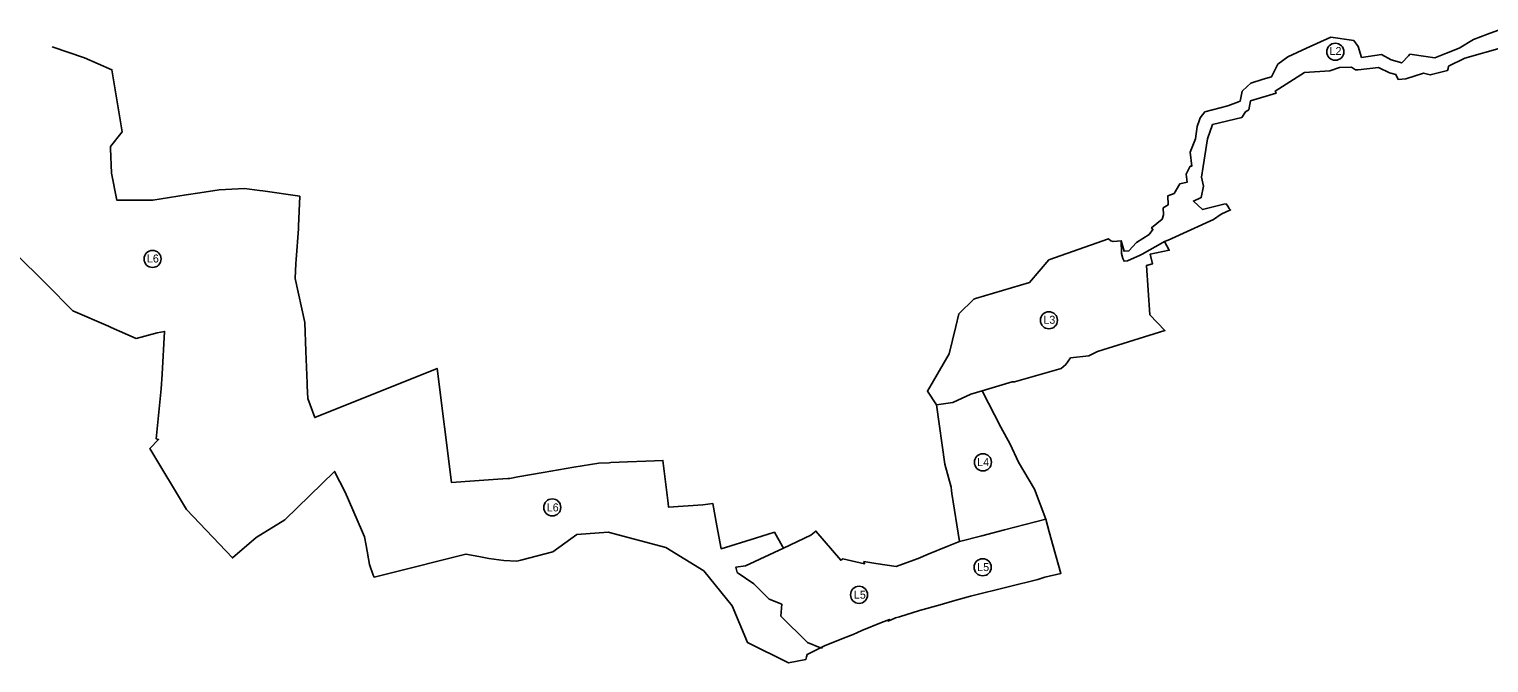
# Model space of a CAD drawing. Extents: x -445081 to -429827, y -1135509 to -1130103.
# Drawn here: x -443832 to -441644, y -1133015 to -1132066 of the extents above; entities that cross this region are included whole.
import ezdxf

# ---------------------------------------------------------------- set-up
doc = ezdxf.new("R2010")
doc.units = 0
for name, color, linetype in [('Vrstva 32', 7, 'Continuous'), ('Vrstva 33', 7, 'Continuous'), ('Vrstva 36', 7, 'Continuous')]:
    doc.layers.add(name, color=color, linetype=linetype)

msp = doc.modelspace()

# ---------------------------------------------------------------- linework, layer by layer
at = {"layer": 'Vrstva 32'}
msp.add_lwpolyline([(-442471.6, -1132628.2), (-442447, -1132625.1), (-442420.2, -1132612.5), (-442403.1, -1132607.3), (-442358.4, -1132593.7), (-442358.4, -1132593.7), (-442354.7, -1132593.7), (-442284.9, -1132574), (-442277.9, -1132567.9), (-442270.6, -1132557.9), (-442243.2, -1132554.9), (-442230.4, -1132548.5), (-442129.2, -1132516.8), (-442151.6, -1132493.3), (-442156.8, -1132419.4), (-442147.8, -1132417.1), (-442151.1, -1132402.4), (-442122.6, -1132396.7), (-442129.7, -1132383.8), (-442132.1, -1132384.9), (-442163.5, -1132402.4), (-442166.4, -1132404.1), (-442185.4, -1132412.8), (-442190.5, -1132413.2), (-442190.5, -1132413.2), (-442192.4, -1132409.2), (-442194.2, -1132401.6), (-442194.6, -1132382.5), (-442206.7, -1132383.5), (-442210.1, -1132382.7), (-442213.7, -1132379.6), (-442303.1, -1132411), (-442332, -1132445), (-442413.2, -1132469.2), (-442415.9, -1132470.2), (-442438.4, -1132492.1), (-442442.6, -1132510.8), (-442452.5, -1132552.2), (-442485.4, -1132607.7)], close=True, dxfattribs=at)
for points in [[(-442485.4, -1132607.7), (-442471.6, -1132628.2), (-442447, -1132625.1), (-442420.2, -1132612.5), (-442403.1, -1132607.3), (-442358.4, -1132593.7), (-442354.7, -1132593.7), (-442284.9, -1132574), (-442277.9, -1132567.9), (-442270.6, -1132557.9), (-442243.2, -1132554.9), (-442230.4, -1132548.5), (-442129.2, -1132516.8), (-442151.6, -1132493.3), (-442156.8, -1132419.4), (-442147.8, -1132417.1), (-442151.1, -1132402.4), (-442122.6, -1132396.7), (-442129.7, -1132383.8), (-442132.1, -1132384.9), (-442163.5, -1132402.4), (-442166.4, -1132404.1), (-442185.4, -1132412.8), (-442190.5, -1132413.2), (-442192.4, -1132409.2), (-442194.2, -1132401.6), (-442194.6, -1132382.5), (-442206.7, -1132383.5), (-442210.1, -1132382.7), (-442213.7, -1132379.6), (-442303.1, -1132411), (-442332, -1132445), (-442413.2, -1132469.2), (-442415.9, -1132470.2), (-442438.4, -1132492.1), (-442442.6, -1132510.8), (-442452.5, -1132552.2), (-442485.4, -1132607.7)], [(-442309, -1132886.8), (-442285.2, -1132881.1), (-442296.6, -1132840.1), (-442302.5, -1132818.9), (-442307.9, -1132799.8), (-442369.7, -1132815.7), (-442403.5, -1132824.5), (-442437.2, -1132833.3), (-442454.6, -1132840.1), (-442484, -1132852.3), (-442499.3, -1132858.8), (-442522.6, -1132867.2), (-442532.1, -1132870.8), (-442562.6, -1132866.1), (-442580.6, -1132863.3), (-442579.6, -1132866.6), (-442612, -1132859.2), (-442615.2, -1132861.2), (-442652.5, -1132817.5), (-442660.2, -1132823.9), (-442701.1, -1132843), (-442758.2, -1132869.6), (-442772.4, -1132871.4), (-442770.3, -1132879.6), (-442745.5, -1132896.6), (-442722.7, -1132919.5), (-442703.6, -1132927.2), (-442704.9, -1132945.1), (-442665, -1132984.7), (-442645.8, -1132992.7), (-442643.5, -1132991.5), (-442639.5, -1132989.6), (-442611.1, -1132978), (-442596.7, -1132972.3), (-442583.4, -1132966.7), (-442554.2, -1132954.6), (-442542.3, -1132949.9), (-442544.6, -1132952.4), (-442540.7, -1132951), (-442532.9, -1132947.8), (-442527, -1132946), (-442497.2, -1132936.8), (-442466.4, -1132928.3), (-442447.5, -1132922.7), (-442420.8, -1132914.9), (-442364.2, -1132900.9), (-442319.8, -1132890.2), (-442309, -1132886.8)], [(-442285.2, -1132881.1), (-442296.6, -1132840.1), (-442302.5, -1132818.9), (-442307.9, -1132799.8), (-442307.9, -1132799.8), (-442369.7, -1132815.7), (-442403.5, -1132824.5), (-442403.5, -1132824.5), (-442437.2, -1132833.3), (-442454.6, -1132840.1), (-442484, -1132852.3), (-442499.3, -1132858.8), (-442522.6, -1132867.2), (-442532.1, -1132870.8), (-442562.6, -1132866.1), (-442580.6, -1132863.3), (-442579.6, -1132866.6), (-442612, -1132859.2), (-442615.2, -1132861.2), (-442652.5, -1132817.5), (-442660.2, -1132823.9), (-442660.2, -1132823.9), (-442701.1, -1132843), (-442758.2, -1132869.6), (-442758.2, -1132869.6), (-442772.4, -1132871.4), (-442770.3, -1132879.6), (-442745.5, -1132896.6), (-442722.7, -1132919.5), (-442703.6, -1132927.2), (-442704.9, -1132945.1), (-442665, -1132984.7), (-442645.8, -1132992.7), (-442642.5, -1132992.5)]]:
    msp.add_lwpolyline(points, dxfattribs=at)
at = {"layer": 'Vrstva 33'}
for points in [[(-442194.6, -1132382.5), (-442190.4, -1132398.3), (-442183.1, -1132397.7), (-442172, -1132385.1), (-442152.9, -1132373.3), (-442147.1, -1132365.7), (-442149.2, -1132363), (-442133.5, -1132350.3), (-442131.5, -1132343.5), (-442131.9, -1132333.2), (-442124.4, -1132328.7), (-442124.8, -1132315.1), (-442115.4, -1132311.6), (-442106.8, -1132297.2), (-442095.8, -1132294.5), (-442097.1, -1132282.6), (-442091.2, -1132270.8), (-442088.8, -1132270.5), (-442091.5, -1132249.7), (-442083.1, -1132229.6), (-442080.6, -1132211.1), (-442077.8, -1132202.9), (-442076.1, -1132198.1), (-442069.2, -1132189.5), (-442035, -1132180.3), (-442018.8, -1132174.2), (-442016.2, -1132173.2), (-442013.2, -1132158.4), (-442005.7, -1132151.3), (-442000.4, -1132146.2), (-441982, -1132140.6), (-441969.2, -1132136.8), (-441960.1, -1132118.1), (-441944.8, -1132106.9), (-441916.7, -1132094), (-441880.5, -1132077.3), (-441846.1, -1132082.3), (-441839.3, -1132091.3), (-441834.4, -1132107.8), (-441804.5, -1132103.5), (-441790.2, -1132111.6), (-441774.1, -1132116), (-441764, -1132105.2), (-441761.9, -1132102.9), (-441737.8, -1132106.4), (-441724.3, -1132108.4), (-441707.1, -1132101.5), (-441688.2, -1132093.9), (-441666.7, -1132080.9), (-441666.7, -1132080.9), (-441645.6, -1132073.1), (-441624.9, -1132065.5)], [(-443797.6, -1132091.8), (-443748.9, -1132108.2), (-443748.9, -1132108.2), (-443707.9, -1132126.3), (-443692.6, -1132219.1), (-443692.6, -1132219.1), (-443710.2, -1132241.2), (-443710.1, -1132244.3), (-443708.7, -1132281), (-443700.4, -1132321.8), (-443646.8, -1132321.8), (-443596.6, -1132313.9), (-443576.1, -1132310.6), (-443547.1, -1132306), (-443509, -1132304), (-443486.5, -1132307.1), (-443481.6, -1132307.8), (-443426.4, -1132315.9), (-443428.4, -1132360.5), (-443428.3, -1132364.5), (-443431.7, -1132410.4), (-443432.1, -1132416.4), (-443433.4, -1132439.1), (-443418.8, -1132505.1), (-443417.1, -1132548.1), (-443415.2, -1132596), (-443415, -1132599.7), (-443414.3, -1132618.9), (-443403.8, -1132647.4), (-443220.4, -1132573.8), (-443199, -1132744.6), (-443199, -1132744.6), (-443164.2, -1132742.2), (-443129.3, -1132739.8), (-443114.3, -1132738.9), (-443111.3, -1132738.6), (-443099.5, -1132736.5), (-443061.5, -1132729.8), (-443061.5, -1132729.8), (-443061.5, -1132729.8), (-443015.2, -1132721.8), (-442977.8, -1132715.9), (-442962.3, -1132715.2), (-442959.8, -1132714.9), (-442935.1, -1132714), (-442907.7, -1132712.9), (-442894.7, -1132712.4), (-442881.8, -1132711.8), (-442874.1, -1132775.7), (-442873.5, -1132781.6), (-442822.1, -1132778.2), (-442806.9, -1132776.4), (-442800.9, -1132809.5), (-442794.6, -1132844), (-442743.2, -1132828), (-442714.7, -1132819.2), (-442714.7, -1132819.2), (-442702.4, -1132840.6), (-442701.1, -1132843)], [(-441623, -1132093), (-441679.7, -1132109.1), (-441679.7, -1132109.1), (-441703.9, -1132121.1), (-441704.7, -1132124.2), (-441705.4, -1132127.2), (-441731.3, -1132133.9), (-441741.6, -1132131.3), (-441768.2, -1132139.7), (-441779.6, -1132140.8), (-441782.8, -1132133.6), (-441792.7, -1132130.8), (-441809.2, -1132122.8), (-441839.7, -1132126.2), (-441843.4, -1132126.6), (-441849.5, -1132122.5), (-441867.2, -1132122.8), (-441881.8, -1132128), (-441919.7, -1132130.2), (-441925.5, -1132133.9), (-441963.7, -1132158.2), (-441962.5, -1132161.6), (-442000.9, -1132172.9), (-442003.5, -1132186.2), (-442008.5, -1132189.4), (-442013.7, -1132197.7), (-442057.7, -1132208.4), (-442065.5, -1132229.9), (-442071.7, -1132271.2), (-442074.1, -1132287), (-442071.5, -1132300.9), (-442074.6, -1132317.9), (-442086.4, -1132323), (-442072.7, -1132335.8), (-442041.1, -1132327.7), (-442037.4, -1132327.3), (-442034.9, -1132330.7), (-442032.7, -1132334), (-442030.8, -1132336.4), (-442045, -1132342.9), (-442056.5, -1132350.9), (-442124.4, -1132381.4), (-442129.7, -1132383.8)], [(-442645.8, -1132992.7), (-442648.5, -1132994), (-442665.8, -1133002.6), (-442666.7, -1133006), (-442667.8, -1133010.1), (-442693.6, -1133014.9), (-442755.1, -1132984.5), (-442778, -1132929.5), (-442820.7, -1132876.9), (-442877.4, -1132842.4), (-442963.8, -1132819.4), (-443011, -1132822.8), (-443046.8, -1132848.6), (-443095, -1132861.1), (-443101, -1132862.6), (-443120.6, -1132861.5), (-443143, -1132858.5), (-443157.7, -1132855.7), (-443177.3, -1132852.1), (-443207.3, -1132859.6), (-443264.6, -1132874), (-443314.9, -1132886.6), (-443316.1, -1132883.4), (-443321.9, -1132867.7), (-443327, -1132839), (-443329.2, -1132826.1), (-443332.2, -1132819.2), (-443333.7, -1132815.9), (-443333.7, -1132815.9), (-443333.7, -1132815.9), (-443333.7, -1132815.9), (-443358.3, -1132759.2), (-443374.2, -1132728.1), (-443374.2, -1132728.1), (-443448.7, -1132800.5), (-443491.7, -1132827.4), (-443527.2, -1132857.8), (-443596, -1132785.4), (-443651, -1132694), (-443638, -1132680.3), (-443638, -1132680.3), (-443641.5, -1132679.3), (-443633.9, -1132604.4), (-443633.9, -1132604.4), (-443632.6, -1132582.2), (-443632.6, -1132582.2), (-443629, -1132518.3), (-443629, -1132518.3), (-443639.9, -1132520.7), (-443671.8, -1132528.9), (-443709.2, -1132512.6), (-443713.3, -1132510.7), (-443713.3, -1132510.7), (-443713.3, -1132510.7), (-443766.7, -1132487.4), (-443806.2, -1132447.4), (-443853.9, -1132399.9)], [(-442403.1, -1132607.3), (-442375.2, -1132661.9), (-442361.4, -1132687.1), (-442348.8, -1132714.2), (-442324.9, -1132754.9), (-442307.9, -1132799.8)], [(-442437.2, -1132833.3), (-442448.5, -1132761.2), (-442449.1, -1132756.8), (-442449.9, -1132751.7), (-442459, -1132717.2), (-442471.6, -1132628.2)]]:
    msp.add_lwpolyline(points, dxfattribs=at)
at = {"layer": 'Vrstva 36'}
for centre in [(-441873.7, -1132099.3), (-443647, -1132409.8), (-442303.1, -1132501.7), (-442402, -1132714.5), (-443047.7, -1132782.1), (-442402.4, -1132871.8), (-442587.8, -1132913.1)]:
    msp.add_circle(centre, 12.8, dxfattribs=at)

# ---------------------------------------------------------------- texts
for s, p in [('L2', (-441882.3, -1132104.2)), ('L6', (-443655.5, -1132415.1)), ('L3', (-442311.4, -1132506.9)), ('L4', (-442410.6, -1132720.2)), ('L6', (-443056, -1132788.1)), ('L5', (-442410.6, -1132877.5)), ('L5', (-442595.5, -1132918.9))]:
    msp.add_text(s, height=12, dxfattribs=at).set_placement(p)

doc.saveas('drawing.dxf')
